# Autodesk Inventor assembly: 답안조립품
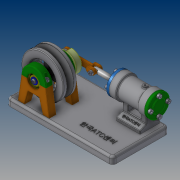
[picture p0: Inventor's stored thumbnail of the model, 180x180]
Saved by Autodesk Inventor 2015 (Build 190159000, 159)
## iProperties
Created: 2018-01
Part Number: 답안조립품
Document SubType Name: Assembly
Designer: SCD-A03
Author: SCD-A03
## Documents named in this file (19)
- C:\Users\SCD-A03\Desktop\380108V1021\답안조립품.iam
- C:\Users\SCD-A03\Desktop\380108V1021\플레이트.ipt
- C:\Users\SCD-A03\Desktop\380108V1021\3mm 와셔.ipt
- C:\Users\SCD-A03\Desktop\380108V1021\V-벨트풀리.ipt
- C:\Users\SCD-A03\Desktop\380108V1021\둥근머리볼트 M3x12.ipt
- C:\Users\SCD-A03\Desktop\380108V1021\베어링 8x22x7.ipt
- C:\Users\SCD-A03\Desktop\380108V1021\베어링커버-A.ipt
- C:\Users\SCD-A03\Desktop\380108V1021\볼트 M3x8.ipt
- C:\Users\SCD-A03\Desktop\380108V1021\볼트 M3x12.ipt
- C:\Users\SCD-A03\Desktop\380108V1021\스페이서.ipt
- C:\Users\SCD-A03\Desktop\380108V1021\지지대-A.ipt
- C:\Users\SCD-A03\Desktop\380108V1021\커넥팅로드-A.ipt
- C:\Users\SCD-A03\Desktop\380108V1021\커넥팅로드-B.ipt
- C:\Users\SCD-A03\Desktop\380108V1021\크랭크축.ipt
- C:\Users\SCD-A03\Desktop\380108V1021\플랜지.ipt
- C:\Users\SCD-A03\Desktop\380108V1021\피스톤.ipt
- C:\Users\SCD-A03\Desktop\380108V1021\하우징.ipt
- C:\Users\SCD-A03\Desktop\380108V1021\하우징커버-A.ipt
- C:\Users\SCD-A03\Desktop\380108V1021\하우징커버-B.ipt
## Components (9 placed, 8 different names)
1. 플레이트:1 — 각도:2
2. 3mm 와셔:1
3. V-벨트풀리:1
4. 플랜지:1
5. 피스톤:1
6. 하우징:1
7. 하우징커버-A:1
8. 하우징커버-B:1
9. 3mm 와셔:2
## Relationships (1: Angle 1)
- 각도:2 [Angle]: 플레이트:1
